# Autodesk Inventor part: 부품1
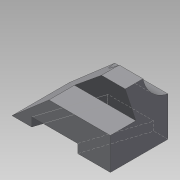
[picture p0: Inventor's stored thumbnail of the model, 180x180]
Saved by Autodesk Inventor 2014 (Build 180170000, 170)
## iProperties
Created: 2015-04
Part Number: 부품1
Material: Generic
Document SubType Name: Modeling
Designer: 203-10
Density: 1 g/cm^3
Appearance: Default
Author: 203-10
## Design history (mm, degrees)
sketch "스케치2"
  geometry: L1 (144, -97)-(9, -97); L2 (9, -97)-(9, -8); L3 (9, -8)-(41.617, -8); L4 (41.617, -8)-(144, -97); 1 further point
  constraints: 8 end point, 1 horizontal, 1 parallel, 1 perpendicular
  dimensions: "d0" = 89 distance of L1.end L2.end; "d1" = 135 distance of L1.start L1.end; "d2" = 139 deg angle of L1 L4; "d4" = 8 distance from line of L3 point (0, 0); "d5" = 9 distance from line of L2 point (0, 0)
extrude "돌출1" new body sketch "스케치2" stored distance "d6" = 79; taper "d7" = 0 deg
sketch "스케치3"
  geometry: L1 (0, 79)-(0, 0) reference; L2 (-89, 79)-(0, 79) reference; L3 (-89, 79)-(-89, 0) reference; L4 (0, 0)-(-89, 0) reference; L5 (-44, 0)-(-44, 35); L6 (-44, 35)-(-89, 20.379); L7 (-44, 0)-(-89, 0); L8 (-89, 20.379)-(-89, 0); C1 r 44 at (-97, 88); 1 further point
  constraints: 8 end point, 2 collinear, 2 point on line, 1 centre point, 1 perpendicular, 1 vertical alignment
  dimensions: "d8" = 44 radius of C1; "d9" = 9 distance from line of L2 C1.centre; "d10" = 44 distance between parallel lines of L1 L5; "d11" = 72 deg angle of L6 L5; "d12" = 35 distance of L5.start L5.end
extrude "돌출2" cut sketch "스케치3" stored distance "d13" = 79; taper "d14" = 0 deg
sketch "스케치4"
  geometry: L1 (0, 0)-(135, 0) reference; L2 (135, -79)-(0, -79) reference; L3 (108, -79)-(82.331, 0); L4 (44.912, -79)-(19.244, 0); L5 (82.331, 0)-(19.244, 0); L6 (44.912, -79)-(108, -79); 1 further point
  constraints: 8 end point, 4 point on line, 2 parallel, 1 collinear
  dimensions: "d15" = 27 distance of L2.start L3.start; "d16" = 60 distance between parallel lines of L4 L3; "d17" = 72 deg angle of L4 L1
extrude "돌출3" cut sketch "스케치4" distance "d18" = 12; taper "d19" = 0 deg
node "솔리드1"
